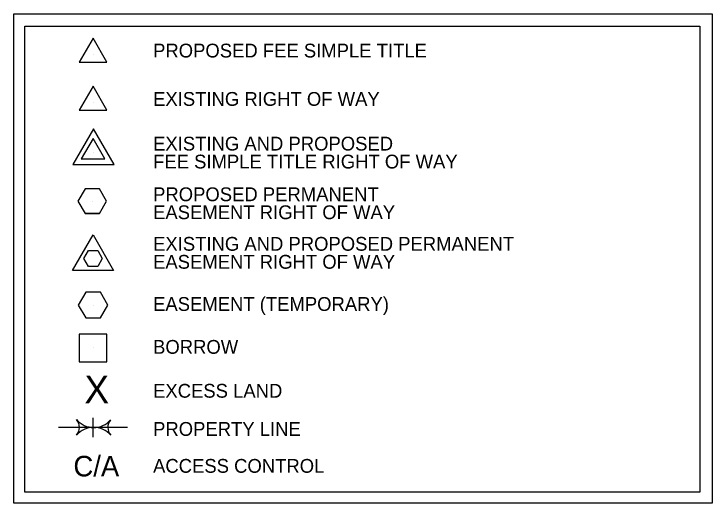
# Model space of a CAD drawing. Extents: x -507127 to -501139, y -509578 to -506434.
# Drawn here: x -505316 to -504684, y -509578 to -509135 of the extents above; entities that cross this region are included whole.
import ezdxf

# ---------------------------------------------------------------- set-up
doc = ezdxf.new("R2010")
doc.units = 0
doc.layers.add('Default', color=7, linetype='Continuous')
doc.layers.add('rowdsnConstructCell', color=7, linetype='Continuous')

# ---------------------------------------------------------------- blocks, each defined once
blk = doc.blocks.new('PE intersecting Existing ROW')
at = {"layer": 'Default'}
for p, q in [((-7.75, -4.47), (0, 8.95)), ((0, 8.95), (7.75, -4.47)), ((-3.5, 0), (-1.75, 3.03)), ((-1.75, 3.03), (1.75, 3.03)), ((1.75, 3.03), (3.5, 0)), ((-1.75, -3.03), (-3.5, 0)), ((3.5, 0), (1.75, -3.03)), ((7.75, -4.47), (-7.75, -4.47)), ((1.75, -3.03), (-1.75, -3.03))]:
    blk.add_line(p, q, dxfattribs=at)

msp = doc.modelspace()

# ---------------------------------------------------------------- linework, layer by layer
at = {"layer": 'rowdsnConstructCell'}
for p, q in [((-505244.5, -509171.41), (-505244.5, -509171.41)), ((-505244.5, -509214.79), (-505244.5, -509214.79)), ((-505244.51, -509259.99), (-505244.51, -509259.99)), ((-505245.28, -509304.53), (-505245.28, -509304.53)), ((-505238.78, -509315.79), (-505251.78, -509315.79)), ((-505244.5, -509398.5), (-505244.5, -509398.5)), ((-505244.5, -509437.39), (-505244.5, -509437.39)), ((-505244.5, -509509.43), (-505244.5, -509500.66)), ((-505213.25, -509509.43), (-505275.76, -509509.43)), ((-505244.51, -509509.43), (-505244.51, -509509.43)), ((-505244.5, -509518.2), (-505244.5, -509509.43)), ((-505244.32, -509509.36), (-505244.32, -509509.36))]:
    msp.add_line(p, q, dxfattribs=at)
for points in [[(-505316.12, -509135.02), (-504683.97, -509135.02), (-504683.97, -509577.73), (-505316.12, -509577.73)], [(-505306.15, -509145.99), (-504694.94, -509145.99), (-504694.94, -509567.76), (-505306.15, -509567.76)], [(-505257, -509178.63), (-505232, -509178.63), (-505244.5, -509156.98)], [(-505257, -509222.01), (-505232, -509222.01), (-505244.5, -509200.35)], [(-505262.82, -509271.4), (-505225.32, -509271.4), (-505244.07, -509238.93)], [(-505255.13, -509266.12), (-505233.88, -509266.12), (-505244.51, -509247.72)], [(-505251.78, -509315.79), (-505238.78, -509315.79), (-505232.28, -509304.53), (-505238.78, -509293.27), (-505251.78, -509293.27), (-505258.28, -509304.53)], [(-505257, -509449.89), (-505232, -509449.89), (-505232, -509424.89), (-505257, -509424.89)]]:
    msp.add_lwpolyline(points, close=True, dxfattribs=at)
msp.add_lwpolyline([(-505251.17, -509410.05), (-505237.84, -509410.05), (-505231.17, -509398.5), (-505237.84, -509386.96), (-505251.17, -509386.96), (-505257.84, -509398.5), (-505251.17, -509410.05)], dxfattribs=at)
for centre, radius, start, end in [((-505267.44, -509509.16), 10.63, 318.46008, 40.93465), ((-505244, -509489.28), 20.11, 219.9762, 319.74739), ((-505220.13, -509509.18), 10.97, 140.97973, 220.82969), ((-505243.99, -509530.03), 20.71, 41.30244, 138.42453)]:
    msp.add_arc(centre, radius, start, end, dxfattribs=at)

# ---------------------------------------------------------------- block references
at = {"layer": 'rowdsnConstructCell', "xscale": 2.4, "yscale": 2.4}
msp.add_blockref('PE intersecting Existing ROW', (-505244.5, -509356.38), dxfattribs=at)

# ---------------------------------------------------------------- texts
at = {"layer": 'rowdsnConstructCell'}
for s, height, p in [('PROPOSED FEE SIMPLE TITLE', 12.5, (-505190.15, -509174.42)), ('EXISTING RIGHT OF WAY', 12.5, (-505190.15, -509218.19)), ('EXISTING AND PROPOSED', 12.5, (-505190.15, -509258.63)), ('FEE SIMPLE TITLE RIGHT OF WAY', 12.5, (-505190.15, -509274.9)), ('PROPOSED PERMANENT', 12.5, (-505190.15, -509304.49)), ('EASEMENT RIGHT OF WAY', 12.5, (-505190.15, -509320.77)), ('EXISTING AND PROPOSED PERMANENT', 12.5, (-505190.15, -509349.36)), ('EASEMENT RIGHT OF WAY', 12.5, (-505190.15, -509365.64)), ('EASEMENT (TEMPORARY)', 12.5, (-505190.15, -509403.82)), ('BORROW', 12.5, (-505190.15, -509442.64)), ('X', 25, (-505252.28, -509487.4)), ('EXCESS LAND', 12.5, (-505190.15, -509482.38)), ('PROPERTY LINE', 12.5, (-505190.15, -509516.9)), ('C/A', 18.622, (-505262.28, -509553.64)), ('ACCESS CONTROL', 12.5, (-505190.15, -509550.35))]:
    msp.add_text(s, height=height, dxfattribs=at).set_placement(p)

doc.saveas('drawing.dxf')
